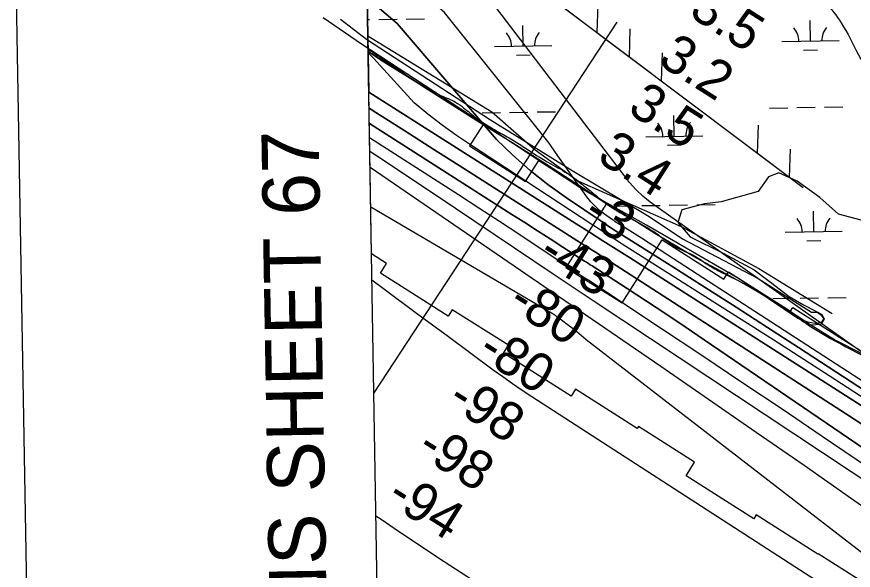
# Model space of a CAD drawing. Extents: x 3887375 to 3925618, y 296674 to 322633.
# Drawn here: x 3890796 to 3892257, y 315401 to 316367 of the extents above; entities that cross this region are included whole.
import ezdxf

# ---------------------------------------------------------------- set-up
doc = ezdxf.new("R2010")
doc.units = 0
for name, color, linetype in [('V-ANNO-SYMB', 7, 'Continuous'), ('V-ANNO-TEXT', 7, 'Continuous'), ('V-GRID-FRAM', 7, 'Continuous'), ('V-RIVR-EDGE', 7, 'Continuous'), ('V-RIVR-JETY', 7, 'Continuous'), ('V-RIVR-RANG', 7, 'Continuous'), ('V-RRAP-FSHR', 7, 'Continuous'), ('V-RRAP-RVMT', 7, 'Continuous'), ('V-TOPO-DPTH', 7, 'Continuous'), ('V-TOPO-MAJR', 7, 'Continuous'), ('V-TOPO-MINR', 7, 'Continuous'), ('V-TOPO-SHOR', 7, 'Continuous'), ('V-TOPO-WATR', 7, 'Continuous'), ('V-WETL-SWMP', 7, 'Continuous')]:
    doc.layers.add(name, color=color, linetype=linetype)

msp = doc.modelspace()

# ---------------------------------------------------------------- linework, layer by layer
at = {"layer": 'V-ANNO-SYMB'}
msp.add_lwpolyline([(3891112.5, 297929.5), (3924190.8, 298497.3), (3923797.5, 321410.5), (3890719.2, 320842.7), (3891112.5, 297929.5)], dxfattribs=at)
at = {"layer": 'V-GRID-FRAM'}
msp.add_lwpolyline([(3891343.3, 320285.8), (3923192.8, 320832.5), (3923512.8, 302652.9), (3891647.4, 302105.9), (3891343.3, 320285.8)], dxfattribs=at)
at = {"layer": 'V-RIVR-EDGE'}
for points in [[(3891409.8, 316310.6), (3891442.6, 316288.7), (3891484, 316260.7), (3891536.5, 316229.9), (3891562.4, 316218.2), (3891576.7, 316208.2), (3891598.6, 316190.7), (3891622.5, 316175), (3891643.6, 316162.6), (3891668.2, 316148.6), (3891679.8, 316141), (3891728.7, 316110.6), (3891760.9, 316091.8), (3891784, 316074.2), (3891797.5, 316063.8), (3891817, 316047.4), (3891844.5, 316028.6), (3891883.5, 316007), (3891908.6, 315992.2), (3891928.4, 315977.8)], [(3891928.4, 315977.8), (3891957.1, 315960.2), (3891975, 315952.6), (3891990.1, 315943.4), (3892009.6, 315930.6), (3892033.9, 315917.8), (3892077.7, 315895.3), (3892112.3, 315874.1), (3892145.7, 315852.5), (3892174, 315832.5), (3892316.1, 315752.5), (3892341.1, 315737.7), (3892375.4, 315721.2), (3892402.4, 315708.8), (3892426.7, 315696), (3892453.8, 315682.4), (3892471.3, 315672), (3892523, 315638.8), (3892560, 315617.6), (3892582.3, 315601.2), (3892604.6, 315586.8), (3892621.3, 315577.2), (3892636, 315565.6), (3892664.2, 315537.6), (3892674.2, 315522.8), (3892678.1, 315511.7), (3892682.1, 315505.3), (3892690.5, 315500.9), (3892696.8, 315498.5), (3892706.8, 315489.3), (3892723.5, 315474.5), (3892741.8, 315455.7), (3892761.6, 315438.1), (3892777.5, 315422.5), (3892805.4, 315399.4), (3892826.5, 315384.6), (3892845.6, 315369.4), (3892875, 315345), (3892902.8, 315321.4), (3892934.6, 315289.8), (3892954.5, 315270.7), (3892974, 315257.5), (3892987.5, 315247.1), (3892996.7, 315235.9), (3893002.6, 315225.5), (3893020.5, 315215.5), (3893037.7, 315206.7), (3893043.6, 315202.3), (3893054.8, 315193.5), (3893076.3, 315182.7), (3893089, 315175.5), (3893097.7, 315167.1), (3893110.9, 315156.7), (3893119.6, 315149.5), (3893128.8, 315145.5), (3893137.5, 315143.5), (3893147.5, 315138.3), (3893165, 315124.7), (3893182.9, 315109.1), (3893204, 315093.9), (3893217.5, 315085.9), (3893226.6, 315076.7), (3893239.4, 315067.9), (3893248.5, 315057.5), (3893272, 315035.9), (3893289.9, 315023.5), (3893300.2, 315019.9), (3893307.8, 315012.3), (3893318.1, 315003.5), (3893337.2, 314990), (3893344.8, 314984), (3893355.1, 314972.4), (3893362.7, 314966.4), (3893374.6, 314961.6), (3893394.9, 314948.8), (3893412.4, 314934.8), (3893439.1, 314915.6), (3893461.3, 314899.6), (3893504.7, 314873.6), (3893525, 314860.8), (3893540.5, 314849.2), (3893560, 314836.4), (3893578.3, 314827.9), (3893587.1, 314821.5), (3893592.6, 314816), (3893596.2, 314806.8), (3893605.3, 314796.8), (3893632.8, 314774), (3893674.2, 314743.2), (3893704.4, 314718), (3893724.7, 314701.6), (3893740.2, 314687.3), (3893752.5, 314678.1), (3893761.7, 314675.7), (3893769.6, 314674.8), (3893777.6, 314670.8), (3893781.2, 314666.8), (3893784.3, 314657.3), (3893789.1, 314645.7), (3893797, 314635.3), (3893812.1, 314618.9), (3893836.4, 314601.7), (3893870.2, 314576.9), (3893883.4, 314567.7), (3893974.9, 314502.2), (3893984.4, 314489.4), (3893990.7, 314479.8), (3894001.1, 314471.4), (3894027.3, 314450.2), (3894050.4, 314433.4), (3894069.1, 314416.6), (3894089.4, 314396.7), (3894117.6, 314375.1), (3894129.6, 314367.5), (3894149.4, 314351.1), (3894187.6, 314319.5), (3894217.5, 314293.9), (3894236.1, 314278.7), (3894249.7, 314267.9), (3894262.8, 314254), (3894279.1, 314238.4)]]:
    msp.add_spline(points, degree=3, dxfattribs=at)
at = {"layer": 'V-RIVR-JETY'}
msp.add_lwpolyline([(3891361.4, 316362.8), (3891406.9, 316328.1), (3891623.5, 316187.4), (3891766.4, 316098.6), (3891900.7, 316018.5), (3891959.1, 315979.5), (3892091.2, 315910.2), (3892149.7, 315873.4), (3892184.3, 315851.7), (3892195.2, 315851.7), (3892199.5, 315849.6), (3892201.7, 315847.4), (3892206, 315840.9), (3892201.7, 315834.4), (3892195.2, 315832.2), (3892190.8, 315832.2), (3892177.8, 315834.4), (3892160.5, 315840.9), (3892056.6, 315910.2), (3891896.3, 316003.3), (3891783.7, 316066.1), (3891604, 316185.2), (3891398.2, 316319.5), (3891331.1, 316365)], dxfattribs=at)
at = {"layer": 'V-RIVR-RANG'}
msp.add_line((3891844.1, 316357.5), (3891419.9, 315711), dxfattribs=at)
at = {"layer": 'V-RRAP-FSHR'}
for p, q in [((3891810.1, 316339.6), (3891811.8, 316388.4)), ((3891866.1, 316297.5), (3891867.7, 316346.3)), ((3891922, 316255.5), (3891923.7, 316304.3)), ((3892089.9, 316129.3), (3892091.6, 316178.1)), ((3892145.9, 316087.3), (3892147.5, 316136.1))]:
    msp.add_line(p, q, dxfattribs=at)
for points in [[(3891401.4, 316608.7), (3891654.4, 316456.6), (3892169.8, 316069.3)], [(3891530.5, 316531.1), (3891654.4, 316456.6), (3891904, 316269)], [(3891409.4, 316333.6), (3891471.1, 316296.3), (3891626, 316201), (3891701.5, 316135), (3891777, 316080), (3891956.4, 316001.2), (3892092.4, 315927.9), (3892220.1, 315849.6)], [(3892074.4, 316141), (3892169.8, 316069.3)]]:
    msp.add_lwpolyline(points, dxfattribs=at)
at = {"layer": 'V-RRAP-RVMT'}
for p, q in [((3891415.8, 315953.4), (3891409.9, 316307.1)), ((3891409.9, 316307.1), (3891502.6, 316248.2)), ((3891502.6, 316248.2), (3891502.4, 316247.9)), ((3891502.4, 316247.9), (3891610.5, 316179.3)), ((3891610.5, 316179.3), (3891586.7, 316141.9)), ((3891586.7, 316141.9), (3891684.6, 316079.7)), ((3891684.6, 316079.7), (3891708.1, 316116.6)), ((3891708.1, 316116.6), (3891826.2, 316041.5)), ((3891826.2, 316041.5), (3891755.4, 315929.9)), ((3891853.3, 315867.7), (3891923.2, 315977.8)), ((3891923.2, 315977.8), (3892031.2, 315909.3)), ((3891442.2, 315936.6), (3891415.8, 315953.4)), ((3891431.5, 315919.7), (3891442.2, 315936.6)), ((3891755.4, 315929.9), (3891853.3, 315867.7)), ((3891549.6, 315844.6), (3891431.5, 315919.7)), ((3892031.2, 315909.3), (3892039.3, 315921.9)), ((3892039.3, 315921.9), (3892147.3, 315853.3)), ((3891556.9, 315856), (3891549.6, 315844.6)), ((3891654.9, 315793.9), (3891556.9, 315856)), ((3892147.3, 315853.3), (3892151.6, 315860)), ((3892151.6, 315860), (3892269.8, 315784.9)), ((3891646, 315780.1), (3891654.9, 315793.9)), ((3891764.3, 315705.1), (3891646, 315780.1)), ((3891772, 315717.2), (3891764.3, 315705.1)), ((3891880, 315648.7), (3891772, 315717.2)), ((3891882.2, 315652), (3891880, 315648.7)), ((3891980.1, 315589.8), (3891882.2, 315652)), ((3891965.1, 315566.1), (3891980.1, 315589.8)), ((3892083.2, 315491.1), (3891965.1, 315566.1)), ((3892087.5, 315497.8), (3892083.2, 315491.1)), ((3892195.5, 315429.2), (3892087.5, 315497.8)), ((3892196, 315430), (3892195.5, 315429.2)), ((3892294, 315367.7), (3892196, 315430))]:
    msp.add_line(p, q, dxfattribs=at)
at = {"layer": 'V-TOPO-DPTH'}
msp.add_line((3891408.3, 316400.4), (3891411.1, 316235.6), dxfattribs=at)
for points in [[(3892270.2, 315782.9), (3891902.6, 316043.8), (3891889.4, 316054.3), (3891877.1, 316065.6), (3891866.1, 316078.2), (3891855.9, 316091.7), (3891625.3, 316393.6), (3891529.5, 316477), (3891427.4, 316550.3), (3891405.6, 316561.7)], [(3892574.5, 315521.6), (3892161.7, 315790), (3892107.3, 315825.2), (3892052.8, 315860.2), (3891998.2, 315895), (3891943.5, 315929.7), (3891849.6, 315988.8), (3891841.8, 315993.8), (3891834, 315998.8), (3891826.2, 316003.9), (3891818.5, 316009.1), (3891756.2, 316051.2), (3891723.9, 316074.5), (3891692.6, 316099.1), (3891662.8, 316125.4), (3891634, 316152.9), (3891460.8, 316355.1), (3891410.7, 316398.6), (3891408.3, 316400.4)], [(3891408.3, 316400.4), (3891410.7, 316398.6), (3891460.8, 316355.1), (3891634, 316152.9), (3891662.8, 316125.4), (3891692.6, 316099.1), (3891723.9, 316074.5), (3891756.2, 316051.2), (3891818.5, 316009.1), (3891826.2, 316003.9), (3891834, 315998.8), (3891841.8, 315993.8), (3891849.6, 315988.8), (3891943.5, 315929.7), (3891998.2, 315895), (3892052.8, 315860.2), (3892107.3, 315825.2), (3892161.7, 315790), (3892574.5, 315521.6)], [(3891411.1, 316235.6), (3891773.3, 316005.9), (3891796.5, 315991.2), (3891819.8, 315976.4), (3891843, 315961.6), (3891866.3, 315946.8), (3892292, 315675.3)], [(3891411.1, 316235.6), (3891773.3, 316005.9), (3891796.5, 315991.2), (3891819.8, 315976.4), (3891843, 315961.6), (3891866.3, 315946.8), (3892292, 315675.3)], [(3892300.4, 315637.8), (3892245.3, 315673.8), (3891833.1, 315939.3), (3891820.1, 315947.7), (3891807, 315956.1), (3891793.8, 315964.5), (3891780.7, 315972.9), (3891575.2, 316103.6), (3891524.5, 316135.8), (3891473.8, 316168), (3891423.1, 316200.1), (3891411.5, 316207.5)], [(3891411.5, 316207.5), (3891423.1, 316200.1), (3891473.8, 316168), (3891524.5, 316135.8), (3891575.2, 316103.6), (3891780.7, 315972.9), (3891793.8, 315964.5), (3891807, 315956.1), (3891820.1, 315947.7), (3891833.1, 315939.3), (3892245.3, 315673.8), (3892300.4, 315637.8)], [(3892515.7, 315450.3), (3891996.9, 315803.5), (3891963.4, 315826.1), (3891929.9, 315848.5), (3891896.2, 315870.7), (3891862.4, 315892.8), (3891801.2, 315932.3), (3891797.9, 315934.4), (3891794.6, 315936.5), (3891791.2, 315938.7), (3891787.9, 315940.8), (3891750.1, 315965.1), (3891727.8, 315979.4), (3891705.6, 315993.6), (3891683.3, 316007.9), (3891661, 316022.1), (3891412, 316181.1)], [(3891412, 316181.1), (3891661, 316022.1), (3891683.3, 316007.9), (3891705.6, 315993.6), (3891727.8, 315979.4), (3891750.1, 315965.1), (3891787.9, 315940.8), (3891791.2, 315938.7), (3891794.6, 315936.5), (3891797.9, 315934.4), (3891801.2, 315932.3), (3891862.4, 315892.8), (3891896.2, 315870.7), (3891929.9, 315848.5), (3891963.4, 315826.1), (3891996.9, 315803.5), (3892515.7, 315450.3)]]:
    msp.add_lwpolyline(points, dxfattribs=at)
at = {"layer": 'V-TOPO-MAJR'}
msp.add_lwpolyline([(3892521.3, 315419.7), (3892202.7, 315635), (3892132.7, 315682.2), (3892062.7, 315729.2), (3891992.5, 315776), (3891922.2, 315822.7), (3891795.3, 315906.7), (3891788.4, 315911.2), (3891781.5, 315915.8), (3891774.5, 315920.4), (3891767.6, 315925), (3891710.3, 315963), (3891674.7, 315986.4), (3891639, 316009.8), (3891603.3, 316033.1), (3891567.4, 316056.2), (3891412.4, 316155.8)], dxfattribs=at)
at = {"layer": 'V-TOPO-MINR'}
for points in [[(3892571, 315538.7), (3891933.3, 315951.3), (3891918, 315961.2), (3891902.6, 315971), (3891887.2, 315980.8), (3891871.8, 315990.5), (3891845.5, 316006.9), (3891843.2, 316008.4), (3891841, 316009.9), (3891838.7, 316011.4), (3891836.5, 316012.9), (3891822.8, 316022.5), (3891814.2, 316029.2), (3891806.1, 316036.5), (3891798.7, 316044.5), (3891791.9, 316053.1), (3891737.1, 316130.1), (3891726, 316146.7), (3891543, 316374.4), (3891470.1, 316437.8), (3891406.9, 316483.2)], [(3892574.5, 315521.6), (3892161.7, 315790), (3892107.3, 315825.2), (3892052.8, 315860.2), (3891998.2, 315895), (3891943.5, 315929.7), (3891849.6, 315988.8), (3891841.8, 315993.8), (3891834, 315998.8), (3891826.2, 316003.9), (3891818.5, 316009.1), (3891756.2, 316051.2), (3891723.9, 316074.5), (3891692.6, 316099.1), (3891662.8, 316125.4), (3891634, 316152.9), (3891460.8, 316355.1), (3891410.7, 316398.6), (3891408.3, 316400.4)], [(3892311, 315678.6), (3892214.8, 315740.8), (3892118.3, 315802.6), (3892021.7, 315864.1), (3891853.7, 315970.6), (3891840.3, 315979.1), (3891826.9, 315987.7), (3891813.6, 315996.3), (3891800.3, 316004.9), (3891590.3, 316142.5), (3891564.4, 316160.1), (3891539, 316178.2), (3891514.3, 316197.3), (3891490, 316216.9), (3891419.5, 316294.7), (3891409.9, 316304.4)], [(3892292, 315675.3), (3891866.3, 315946.8), (3891843, 315961.6), (3891819.8, 315976.4), (3891796.5, 315991.2), (3891773.3, 316005.9), (3891411.1, 316235.6)], [(3892300.4, 315637.8), (3892245.3, 315673.8), (3891833.1, 315939.3), (3891820.1, 315947.7), (3891807, 315956.1), (3891793.8, 315964.5), (3891780.7, 315972.9), (3891575.2, 316103.6), (3891524.5, 316135.8), (3891473.8, 316168), (3891423.1, 316200.1), (3891411.5, 316207.5)], [(3892515.7, 315450.3), (3891996.9, 315803.5), (3891963.4, 315826.1), (3891929.9, 315848.5), (3891896.2, 315870.7), (3891862.4, 315892.8), (3891801.2, 315932.3), (3891797.9, 315934.4), (3891794.6, 315936.5), (3891791.2, 315938.7), (3891787.9, 315940.8), (3891750.1, 315965.1), (3891727.8, 315979.4), (3891705.6, 315993.6), (3891683.3, 316007.9), (3891661, 316022.1), (3891412, 316181.1)], [(3892453.6, 315440.5), (3891802.8, 315871.4), (3891785.4, 315883), (3891768, 315894.6), (3891750.6, 315906.2), (3891733.2, 315917.8), (3891528.6, 316055.3), (3891480.6, 316087.3), (3891432.5, 316119.1), (3891412.8, 316132)], [(3892466.2, 315377.6), (3892254.3, 315525.9), (3892171.1, 315584), (3892087.8, 315641.8), (3892004.3, 315699.5), (3891920.8, 315756.9), (3891779, 315854), (3891766.2, 315862.8), (3891753.4, 315871.6), (3891740.6, 315880.3), (3891727.9, 315889.1), (3891413.3, 316104.4)], [(3892399.5, 315333.5), (3891790.8, 315803.6), (3891782.6, 315810.5), (3891774.4, 315817.3), (3891766.1, 315823.9), (3891757.6, 315830.4), (3891742.3, 315841.9), (3891741.5, 315842.5), (3891739.7, 315843.8), (3891737.2, 315845.6), (3891734.7, 315847.2), (3891731.1, 315849.5), (3891729.9, 315850.2), (3891414.4, 316035.1)], [(3892277.9, 315328.1), (3892230.3, 315358.6), (3892182.8, 315389.2), (3892135.3, 315419.9), (3891695.9, 315704), (3891678.8, 315715.3), (3891661.8, 315726.8), (3891645.1, 315738.6), (3891628.5, 315750.6), (3891550.1, 315808.4), (3891494.5, 315849.6), (3891438.9, 315890.8), (3891416.6, 315907.5)], [(3891423.4, 315496.6), (3891434.2, 315489.2), (3891461.2, 315470.8), (3891488.3, 315452.6), (3891515.5, 315434.6), (3891542.8, 315416.7), (3891623.7, 315364.1), (3891651.2, 315346.4), (3891678.9, 315328.8), (3891706.7, 315311.4), (3891734.6, 315294.1), (3891762.5, 315276.8), (3891790.3, 315259.4), (3891818, 315241.8), (3891845.6, 315224.1), (3892227, 314976.3), (3892231, 314973.7), (3892234.9, 314971.2), (3892238.8, 314968.7), (3892242.8, 314966.2), (3892267.6, 314950.4)]]:
    msp.add_lwpolyline(points, dxfattribs=at)
at = {"layer": 'V-TOPO-SHOR'}
msp.add_lwpolyline([(3892271, 316012), (3892231.4, 316022.8), (3892199, 316051.6), (3892159.4, 316080.4), (3892127, 316094.8), (3892109, 316087.6), (3892091, 316062.4), (3892026.2, 316044.4), (3891997.4, 316040.8), (3891957.8, 316030), (3891950.6, 316008.4), (3891972.2, 315983.2), (3892029.8, 315954.4), (3892083.8, 315925.6), (3892112.6, 315904), (3892145, 315878.8), (3892170.2, 315864.4), (3892191.8, 315853.6), (3892199.9, 315847.5), (3892206.2, 315839.2), (3892201.1, 315830.3), (3892183.3, 315829.2)], dxfattribs=at)
msp.add_spline([(3891406.7, 317064.9), (3891440, 317012.9), (3891501.9, 316958), (3891556.9, 316921.8), (3891621.4, 316873.5), (3891709.5, 316814.4), (3891784.5, 316780.2), (3891858.8, 316655.7), (3891898.9, 316604.4), (3891955.5, 316546.3), (3892020.9, 316492), (3892101.9, 316452.4), (3892173.4, 316420.2), (3892236.1, 316356.5), (3892266, 316301), (3892313.9, 316188.5), (3892309, 316092.9), (3892292, 316050.6)], degree=3, dxfattribs=at)
at = {"layer": 'V-TOPO-WATR'}
msp.add_lwpolyline([(3892270.2, 315782.9), (3891902.6, 316043.8), (3891889.4, 316054.3), (3891877.1, 316065.6), (3891866.1, 316078.2), (3891855.9, 316091.7), (3891625.3, 316393.6), (3891529.5, 316477), (3891427.4, 316550.3), (3891405.6, 316561.7)], dxfattribs=at)
at = {"layer": 'V-WETL-SWMP'}
for p, q in [((3891409.9, 316306.1), (3891405.8, 316549)), ((3891409, 316362.1), (3891412.3, 316362.1)), ((3891428.3, 316362.4), (3891460.3, 316363)), ((3891476.3, 316363.2), (3891508.3, 316363.8)), ((3891680.4, 316316), (3891679.8, 316352)), ((3892182.3, 316324.6), (3892181.6, 316360.6)), ((3892132.3, 316323.7), (3892232.3, 316325.5)), ((3891432.4, 316291.1), (3891409.9, 316306.1)), ((3891630.4, 316315.1), (3891730.4, 316316.8)), ((3892170.5, 316309), (3892194.5, 316309.4)), ((3891512.4, 316241.1), (3891432.4, 316291.1)), ((3891668.7, 316300.4), (3891692.7, 316300.8)), ((3891562.7, 316209.3), (3891512.4, 316241.1)), ((3891627.8, 316167.9), (3891562.7, 316209.3)), ((3892110.9, 316207.9), (3892142.8, 316208.5)), ((3892158.8, 316208.8), (3892190.8, 316209.3)), ((3892206.8, 316209.6), (3892238.8, 316210.1)), ((3891609, 316199.3), (3891641, 316199.9)), ((3891657, 316200.1), (3891689, 316200.7)), ((3891705, 316201), (3891737, 316201.5)), ((3891944.6, 316158.6), (3891944, 316194.6)), ((3891662.3, 316146.3), (3891627.8, 316167.9)), ((3891894.6, 316157.8), (3891994.6, 316159.5)), ((3891721.2, 316109.2), (3891662.3, 316146.3)), ((3891932.9, 316143), (3891956.9, 316143.4)), ((3891797.4, 316060.2), (3891721.2, 316109.2)), ((3891834.7, 316036.3), (3891797.4, 316060.2)), ((3891878.5, 316009.4), (3891834.7, 316036.3)), ((3891839.8, 316036.8), (3891871.8, 316037.3)), ((3891887.8, 316037.6), (3891919.8, 316038.1)), ((3891935.8, 316038.4), (3891967.8, 316038.9)), ((3891983.8, 316039.2), (3892015.8, 316039.8)), ((3892188, 315992), (3892187.4, 316028)), ((3891910.3, 315988.7), (3891878.5, 316009.4)), ((3891938.9, 315971.9), (3891910.3, 315988.7)), ((3892138, 315991.1), (3892238, 315992.8)), ((3891983.4, 315945.9), (3891938.9, 315971.9)), ((3892176.2, 315976.3), (3892200.2, 315976.8)), ((3892035.8, 315918), (3891983.4, 315945.9)), ((3892071.3, 315898.5), (3892035.8, 315918)), ((3892133.5, 315861.4), (3892071.3, 315898.5)), ((3892116.6, 315875.3), (3892148.6, 315875.9)), ((3892164.6, 315876.1), (3892196.5, 315876.7)), ((3892212.5, 315876.9), (3892244.5, 315877.5)), ((3892183.3, 315829.2), (3892133.5, 315861.4)), ((3892224.6, 315803.7), (3892183.3, 315829.2)), ((3892273.7, 315778.7), (3892224.6, 315803.7))]:
    msp.add_line(p, q, dxfattribs=at)
for centre, start, end in [((3891625.2, 316315.5), 0.2115, 41.7552), ((3891735.7, 316317.4), 140.2115, 181.7552), ((3892127, 316324.1), 0.2115, 41.7552), ((3892237.5, 316326), 140.2115, 181.7552), ((3891889.4, 316158.2), 0.2115, 41.7552), ((3891999.8, 316160.1), 140.2115, 181.7552), ((3892132.7, 315991.5), 0.2115, 41.7552), ((3892243.2, 315993.4), 140.2115, 181.7552)]:
    msp.add_arc(centre, 35.2, start, end, dxfattribs=at)

# ---------------------------------------------------------------- texts
at = {"layer": 'V-ANNO-TEXT'}
msp.add_text('JOINS SHEET 67', height=100, rotation=90.9834, dxfattribs=at).set_placement((3891341.5, 315107))
at = {"layer": 'V-RIVR-RANG'}
for s, rotation, p in [('3.5', 327.5283, (3891967.7, 316370)), ('3.2', 327.5283, (3891914.2, 316285.5)), ('3.5', 327.5283, (3891860.7, 316201)), ('3.4', 327.5283, (3891807.2, 316116.5)), ('-3', 327.5283, (3891781.6, 316014.3)), ('-43', 327.8114, (3891703.5, 315944.9)), ('-80', 327.8114, (3891651.2, 315859.7)), ('-80', 327.8114, (3891597.7, 315775.2)), ('-98', 327.8114, (3891545.3, 315690)), ('-98', 327.8114, (3891491.8, 315605.5)), ('-94', 327.8114, (3891439, 315520.6))]:
    msp.add_text(s, height=67, rotation=rotation, dxfattribs=at).set_placement(p)

doc.saveas('drawing.dxf')
